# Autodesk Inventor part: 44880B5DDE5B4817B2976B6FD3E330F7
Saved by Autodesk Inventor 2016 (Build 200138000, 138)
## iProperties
Created: 2015-08
Part Number: 44880B5DDE5B4817B2976B6FD3E330F7
Material: Steel
Document SubType Name: Modeling
Designer: Ugljesa
Categories: <?xml version="1.0" encoding="UTF-16"?> <MemberInstance><Categories><FamilyTemplate><FamilyTemplateParameter ValueType="xs:double" Id="1" ObjectReferenceKey="da
Density: 1 g/cm^3
Appearance: Steel
CustomPartVersion: 1
Author: Ugljesa
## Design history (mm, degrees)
sketch "Sketch1"
  geometry: C1 r 56.77 at (0, 0)
  constraints: 1 centre point
  dimensions: "d0" = 113.5407 diameter of C1 (= da_da)
extrude "Extrusion1" new body sketch "Sketch1" distance "d1" = 20 (= da_b); taper "d2" = 0 deg
workplane "Work Plane2"
sketch "Sketch2"
  geometry: C1 r 56.77 at (0, 0) reference; C2 r 54.857 at (0, 0)
  constraints: 1 centre point, 1 coincident
  dimensions: "d3" = 109.71429 diameter of C2 (= da_dw)
feature "Pitch Diameter" sketch "Sketch2" dims "d4" = 10, "d5" = 0
workplane "Work Plane8"
workplane "Work Plane9"
feature "Spur Gear" dims "da_b" = 20, "da_d" = 109.06138, "da_aw" = 80, "da_da" = 113.5407, "da_df" = 103.43638, "da_dw" = 109.71429, angle "da_beta" = 8 deg, "da_lefttooth" = 10, "da_righttooth" = 0
body "Solid1"
body "Srf1"
other parameters: "d17" = 0, "d34" = 0.6545 (computed from da_z), "d39" = 0, "d41" = 0, "d47" = 0, "d48" = 0
